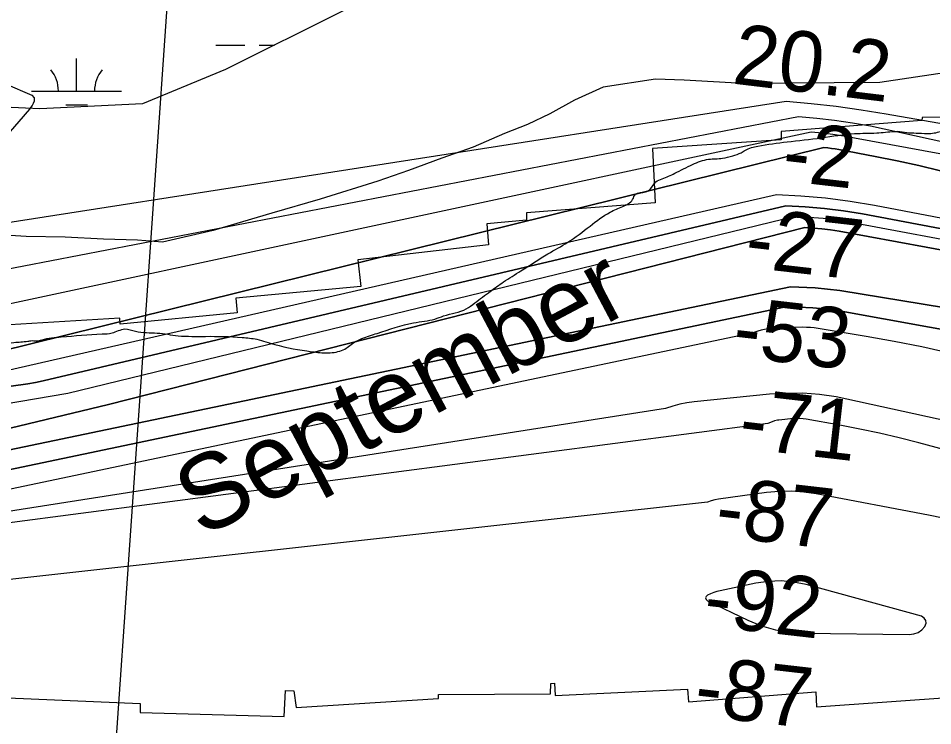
# Model space of a CAD drawing. Extents: x 3445503 to 3483459, y 540493 to 566012.
# Drawn here: x 3466718 to 3467732, y 552212 to 552997 of the extents above; entities that cross this region are included whole.
import ezdxf

# ---------------------------------------------------------------- set-up
doc = ezdxf.new("R2010")
doc.units = 0
for name, color, linetype in [('V-RIVR-EDGE', 7, 'Continuous'), ('V-RIVR-IDEN', 7, 'Continuous'), ('V-RIVR-RANG', 7, 'Continuous'), ('V-RRAP-RVMT', 7, 'Continuous'), ('V-SITE-VEGE', 7, 'Continuous'), ('V-TOPO-DPTH', 7, 'Continuous'), ('V-TOPO-MAJR', 7, 'Continuous'), ('V-TOPO-MINR', 7, 'Continuous'), ('V-TOPO-WATR', 7, 'Continuous'), ('V-WETL-SWMP', 7, 'Continuous')]:
    doc.layers.add(name, color=color, linetype=linetype)

msp = doc.modelspace()

# ---------------------------------------------------------------- linework, layer by layer
at = {"layer": 'V-RIVR-EDGE'}
msp.add_spline([(3466309.4, 552622), (3466349.7, 552619.4), (3466382.7, 552619.3), (3466411.9, 552618.6), (3466431.7, 552619.2), (3466456.4, 552621.2), (3466478.3, 552625.4), (3466500.2, 552626.4), (3466524.2, 552628), (3466536.8, 552627.7), (3466565.6, 552631.8), (3466586.1, 552632.4), (3466600.7, 552633.8), (3466616, 552634.4), (3466639.3, 552633.7), (3466653.6, 552633.6), (3466663.7, 552636.4), (3466671, 552636.7), (3466676.5, 552638.1), (3466689.4, 552636.3), (3466713.4, 552637.3), (3466728.7, 552638.7), (3466733.5, 552639.3), (3466741.2, 552639.3), (3466744.7, 552640.3), (3466765.9, 552643.4), (3466811.1, 552646.8), (3466822.2, 552647.8), (3466836.5, 552652.3), (3466848.3, 552649.8), (3466872.3, 552647.7), (3466895.5, 552644.8), (3466925.8, 552644.1), (3466966.5, 552642.9), (3466982.8, 552640.8), (3467002.6, 552635.2), (3467043.6, 552627.1), (3467061.7, 552625.7), (3467070.7, 552626.7), (3467078.7, 552629.1), (3467090.2, 552637.1), (3467099.3, 552641.6), (3467116.3, 552647.4), (3467156.7, 552659.1), (3467180.3, 552663.3), (3467190, 552666.7), (3467215.1, 552674.6), (3467224.5, 552681.2), (3467241.9, 552694), (3467256.2, 552704.4), (3467275.7, 552716.6), (3467305.6, 552735.6), (3467327.6, 552748.4), (3467352.3, 552766.4), (3467374.6, 552781.7), (3467388.8, 552788.2), (3467399.6, 552795.9), (3467402.8, 552801.8), (3467413.9, 552804.2), (3467419.5, 552807.6), (3467425.4, 552815.3), (3467432.4, 552818.7), (3467446.3, 552824.9), (3467466.1, 552834.6), (3467483.9, 552840.5), (3467499.2, 552841.5), (3467510.7, 552844.3), (3467520, 552847.7), (3467524.6, 552850.5), (3467538.5, 552855), (3467570.8, 552859.7), (3467609.1, 552864.2), (3467645.6, 552868.9), (3467670.3, 552869.6), (3467689.8, 552871.3), (3467696, 552871.3), (3467706.1, 552869.8), (3467716.5, 552869.5), (3467730.4, 552869.1), (3467744.7, 552872.2), (3467757.2, 552874.9), (3467768.3, 552874.9), (3467789.9, 552871.4), (3467862.2, 552872.9), (3467905.6, 552870), (3467943.5, 552856), (3467982, 552836.1), (3468014.6, 552810.7), (3468040.7, 552789.1), (3468070.1, 552766.4), (3468095.1, 552752.4), (3468129.5, 552738.4), (3468159.7, 552729.3), (3468202.1, 552725.4), (3468241.4, 552724.6), (3468263.7, 552723.5), (3468284.5, 552718.6), (3468310.5, 552700.1), (3468339.4, 552679.9), (3468348.4, 552674.3), (3468371.3, 552670), (3468395, 552672.1), (3468423.1, 552672.4), (3468450.6, 552670.5), (3468476.3, 552670.8), (3468493.3, 552672.2), (3468516.3, 552677.3), (3468541.3, 552687.4), (3468560.1, 552697.7), (3468569.5, 552699.5), (3468577.2, 552699.1), (3468586.5, 552693.2), (3468603.2, 552676.1), (3468627.2, 552664.5), (3468668.5, 552659.9), (3468712.7, 552659.1), (3468729.7, 552662.6), (3468746.7, 552667.4), (3468760, 552668.4), (3468773.1, 552661.8), (3468796, 552642.9), (3468815.1, 552632.1), (3468834.6, 552620.2), (3468847.1, 552617.4), (3468885.7, 552611.4), (3468924.9, 552605.1), (3468947.9, 552603.3), (3468956.9, 552605.3), (3468966, 552610.9), (3468970.8, 552616.4), (3468974.7, 552616.4), (3468976.7, 552609.8), (3468983.6, 552592.1), (3468990.6, 552583.7), (3469002.7, 552573.2), (3469014.5, 552565.9), (3469022.2, 552563.1), (3469029.1, 552562.4), (3469038.5, 552560.6), (3469047.9, 552555.4), (3469053.8, 552553.3), (3469073.9, 552550.8), (3469091.3, 552548.3), (3469106.6, 552542), (3469126.7, 552536.4), (3469142.7, 552533.6), (3469153.1, 552532.2), (3469162.5, 552528.3), (3469171.9, 552518.2), (3469185.8, 552509.5), (3469208.7, 552504.6), (3469232.7, 552501.7), (3469258.1, 552503.4), (3469277.2, 552507.5), (3469302.6, 552512.7), (3469341.9, 552520.6), (3469368.3, 552524), (3469396.1, 552521.5), (3469447.9, 552506.1), (3469526, 552476), (3469583.7, 552459.9), (3469651.1, 552445.1), (3469684.8, 552437.7), (3469730.7, 552432.7), (3469767.1, 552428.8), (3469829.7, 552423.4), (3469847.8, 552424.1), (3469856.8, 552424.1), (3469867.6, 552422.3), (3469876.3, 552418.5), (3469887.7, 552412.9), (3469925.6, 552399.2), (3469955.1, 552391.8), (3469977.4, 552385.9), (3470001.3, 552379.6), (3470024.3, 552378.5), (3470048.3, 552381.5), (3470074, 552388.4), (3470084.1, 552390.8), (3470093.8, 552391.5), (3470109.1, 552387.6), (3470138.3, 552373), (3470163.6, 552356.6), (3470192.4, 552345.7), (3470225.5, 552340.4), (3470241.8, 552339.3), (3470271.7, 552339.3), (3470311, 552335.7), (3470330.1, 552335.6), (3470358.6, 552336.3), (3470382.6, 552334.8), (3470398.2, 552331.3), (3470414.5, 552324.7), (3470435, 552316.6), (3470465.6, 552306.1), (3470481.6, 552297), (3470485.4, 552296.3), (3470491.6, 552296), (3470495.8, 552293.5), (3470500, 552290.7), (3470505.9, 552287.9), (3470526.7, 552283), (3470533.3, 552282.7), (3470539.2, 552282.6), (3470542.4, 552281.9), (3470544.1, 552279.5), (3470547.2, 552276.7), (3470551.4, 552273.6), (3470557.6, 552271.8), (3470564.6, 552269.7), (3470576.4, 552270), (3470585.8, 552269.3), (3470591.3, 552266.5), (3470613.6, 552258.5), (3470637.5, 552248), (3470666.7, 552234.4), (3470680.9, 552228.1), (3470696.6, 552223.2), (3470705.2, 552221), (3470710.5, 552221), (3470716.4, 552224.8), (3470726.8, 552226.2), (3470744.9, 552227.9), (3470772, 552229.9), (3470784.2, 552230.6), (3470792.2, 552230.2), (3470802.9, 552227.1), (3470818.6, 552226.7), (3470830.1, 552229.8), (3470836, 552233.6), (3470842.6, 552233.9), (3470861, 552232.8), (3470874.2, 552228.3), (3470890.2, 552221.3), (3470909.3, 552220.5), (3470935.4, 552220.5), (3470949.6, 552223.9), (3470960.8, 552226.3), (3470973.3, 552226.3), (3470997.6, 552221.7), (3471022.3, 552216.4), (3471070.6, 552205.2), (3471089, 552203.4), (3471111.9, 552203), (3471121.7, 552202.6), (3471127.9, 552201.6), (3471132.8, 552198.1), (3471136.6, 552193.2), (3471141.4, 552193.2), (3471145.6, 552196), (3471151.2, 552196.7), (3471156.8, 552196.6), (3471178.3, 552192.1), (3471192.5, 552188.2), (3471223.5, 552180.5), (3471265.8, 552168.6), (3471314.8, 552156.3), (3471351.3, 552145.4), (3471386, 552137), (3471401.3, 552136.6), (3471419.4, 552135.2), (3471433.7, 552132), (3471456.2, 552126.4), (3471476.7, 552123.2), (3471490.6, 552119.3), (3471513.9, 552109.2), (3471547.9, 552099), (3471579.6, 552092), (3471609.4, 552085), (3471637.2, 552078.6), (3471668.5, 552067.4), (3471684.8, 552061.8), (3471699.8, 552059.7), (3471716.4, 552054.5), (3471743.2, 552045.4), (3471759.5, 552035.9), (3471773.4, 552031), (3471788.7, 552023.3), (3471808.5, 552013.9), (3471820.6, 552009), (3471825.8, 552006.2), (3471833.4, 551997.2), (3471837.3, 551992.6), (3471849.4, 551987.4), (3471863.3, 551984.9), (3471900.5, 551985.9), (3471925.9, 551983.7), (3471961.7, 551978.1), (3472004.1, 551970.3), (3472058.3, 551955.6), (3472104.5, 551941.2), (3472151.7, 551925.1), (3472165.6, 551919.9), (3472170.8, 551915.3), (3472181.9, 551909.7), (3472192, 551907.3), (3472200, 551902.4), (3472209, 551898.9), (3472220.1, 551895), (3472235.4, 551890.1), (3472240.6, 551890.1), (3472245.5, 551889.8), (3472259.4, 551886.6), (3472269.4, 551885.2), (3472280.2, 551880.3), (3472294.8, 551878.9), (3472314.3, 551878.1), (3472330.3, 551879.1), (3472344.2, 551880.8), (3472354.3, 551878.7), (3472360.2, 551878.4), (3472367.8, 551879), (3472378.2, 551881.1), (3472386.2, 551881.1), (3472400.5, 551879.3), (3472427.3, 551878.2), (3472454.4, 551882.3), (3472479.8, 551882.9), (3472504.4, 551881.5), (3472524.9, 551881.4), (3472536.4, 551880.7), (3472544.4, 551877.9), (3472549.3, 551875.5), (3472555.2, 551875.4), (3472570.1, 551874.7), (3472580.2, 551875.7), (3472593.4, 551876), (3472610.1, 551875.7), (3472633.7, 551876.3), (3472647.3, 551873.5), (3472654.2, 551870.3), (3472660.1, 551870.3), (3472666.4, 551871.7), (3472682.1, 551871), (3472693.9, 551874.1), (3472707.1, 551879.6), (3472717.9, 551879.9), (3472730.7, 551876.4), (3472741.9, 551876), (3472753.7, 551876.7), (3472772.8, 551883.2), (3472794, 551888.4), (3472814.5, 551891.1), (3472833.3, 551892.8), (3472843.4, 551894.5), (3472860.5, 551899.4), (3472888.3, 551905.6), (3472914, 551910), (3472934.2, 551912.4), (3472958.2, 551913.7), (3472986.3, 551913.7), (3473020.7, 551912.9), (3473048.6, 551912.5), (3473075, 551916.2), (3473094.8, 551921.7), (3473114, 551930.4), (3473134.1, 551940.4), (3473153.3, 551952.2), (3473173.5, 551967.4), (3473183.9, 551974), (3473198.2, 551977.8), (3473219.4, 551975), (3473232.2, 551969), (3473250.3, 551958.5), (3473256.5, 551955.1), (3473269.4, 551952.1)], degree=3, dxfattribs=at)
at = {"layer": 'V-RIVR-RANG'}
msp.add_line((3466910.4, 553408.4), (3466815.3, 552031.7), dxfattribs=at)
at = {"layer": 'V-RRAP-RVMT'}
for points in [[(3468200.7, 552603.7), (3468174.4, 552604.1), (3468177.9, 552877.1), (3468023.7, 552880.9), (3468023.2, 552894.5), (3467863.5, 552892.1), (3467863.5, 552888.5), (3467720.8, 552886.7), (3467720.5, 552883.4), (3467564.5, 552871.2), (3467564.3, 552861.8), (3467421.6, 552852.5)], [(3467421.6, 552852.5), (3467424.7, 552792), (3467281.7, 552780.9), (3467282, 552772.9)], [(3467282, 552772.9), (3467237.8, 552769), (3467239.8, 552745.5), (3467094.7, 552729), (3467098.2, 552699.3), (3466959.6, 552686.5), (3466961, 552670.1), (3466831.2, 552657.6), (3466830.7, 552664.3), (3466696.3, 552656)], [(3467602.6, 552250), (3467603.6, 552233.4), (3467759.6, 552244.3), (3467753.1, 552337.4), (3467871.1, 552339.4), (3467875, 552291.4), (3468016.1, 552292), (3468017, 552266.5), (3468155, 552262.9)], [(3466589, 552268.6), (3466590, 552252.8), (3466706.5, 552261.2), (3466706.6, 552243.3), (3466853.3, 552236.9), (3466853.3, 552227.1), (3467013.2, 552222.5), (3467014.5, 552251.5), (3467024, 552251.2), (3467026.5, 552232.4), (3467184.3, 552242.6), (3467184.1, 552246.9), (3467308.6, 552247.6), (3467308.8, 552259.3)], [(3467308.8, 552259.3), (3467312.8, 552259.6), (3467313.5, 552246), (3467460.6, 552253), (3467461.4, 552239), (3467602.6, 552250)]]:
    msp.add_lwpolyline(points, dxfattribs=at)
at = {"layer": 'V-SITE-VEGE'}
msp.add_lwpolyline([(3467770.2, 552940.1), (3467673.6, 552925.6), (3467521.7, 552924.3), (3467456.8, 552928), (3467425, 552929.1), (3467367, 552920.2), (3467335, 552906), (3467307.7, 552890.9), (3467282.9, 552878.9), (3467257.6, 552869), (3467222.9, 552853.9), (3467188.1, 552841.5), (3467151, 552827.9), (3467117.1, 552816), (3467053.1, 552796), (3466999.4, 552780.5), (3466934.2, 552761.3), (3466878.1, 552748.5), (3466850.5, 552750.8), (3466812.9, 552751.9), (3466770.2, 552754.1), (3466727.1, 552754.8), (3466690.8, 552757)], dxfattribs=at)
at = {"layer": 'V-TOPO-DPTH'}
for points in [[(3468675.4, 552653.6), (3468629.5, 552663.6), (3468583.5, 552674), (3468551.3, 552681.6), (3468521.6, 552688.7), (3467663.3, 552877), (3467643.5, 552880.3), (3467623.6, 552883.3), (3467603.7, 552885.6), (3467583.7, 552887.6), (3466662.5, 552710.1)], [(3468902.4, 552561.7), (3468498.4, 552637.8), (3468490.3, 552639.3), (3468482.1, 552640.9), (3468474, 552642.6), (3468465.9, 552644.3), (3468407.1, 552656.7), (3468018.6, 552753.7), (3467968.3, 552766.8), (3467918, 552780.1), (3467867.8, 552793.5), (3467817.6, 552807.1), (3467765.1, 552821.5), (3467741.1, 552827.7), (3467717.1, 552833.5), (3467692.9, 552838.8), (3467668.7, 552843.6), (3467628.3, 552851.2), (3467624.2, 552851.9), (3467620, 552852.5), (3467615.9, 552853), (3467611.7, 552853.4), (3466656.9, 552617.3)], [(3466656.9, 552617.3), (3467611.7, 552853.4), (3467615.9, 552853), (3467620, 552852.5), (3467624.2, 552851.9), (3467628.3, 552851.2), (3467668.7, 552843.6), (3467692.9, 552838.8), (3467717.1, 552833.5), (3467741.1, 552827.7), (3467765.1, 552821.5), (3467817.6, 552807.1), (3467867.8, 552793.5), (3467918, 552780.1), (3467968.3, 552766.8), (3468018.6, 552753.7), (3468407.1, 552656.7), (3468465.9, 552644.3), (3468474, 552642.6), (3468482.1, 552640.9), (3468490.3, 552639.3), (3468498.4, 552637.8), (3468902.4, 552561.7)], [(3466646.8, 552580.1), (3466728.9, 552591.4), (3466737.4, 552592.9), (3466745.8, 552594.7), (3467569.5, 552788.9), (3467590.9, 552787.8), (3467612.3, 552786), (3467633.5, 552783.2), (3467654.7, 552779.8), (3467909, 552731.7), (3468004, 552713.4), (3468098.9, 552694.7), (3468193.6, 552675.2), (3468288.3, 552655.4), (3468435.6, 552623.9), (3468456.5, 552619.4), (3468477.5, 552615), (3468498.5, 552610.6), (3468519.5, 552606.3), (3468633.1, 552582.9), (3468710.9, 552566.8)], [(3466646.8, 552580.1), (3466728.9, 552591.4), (3466737.4, 552592.9), (3466745.8, 552594.7), (3467569.5, 552788.9), (3467590.9, 552787.8), (3467612.3, 552786), (3467633.5, 552783.2), (3467654.7, 552779.8), (3467909, 552731.7), (3468004, 552713.4), (3468098.9, 552694.7), (3468193.6, 552675.2), (3468288.3, 552655.4), (3468435.6, 552623.9), (3468456.5, 552619.4), (3468477.5, 552615), (3468498.5, 552610.6), (3468519.5, 552606.3), (3468633.1, 552582.9), (3468710.9, 552566.8)], [(3469058.5, 552438.2), (3468619.7, 552554.3), (3468583, 552562.7), (3468546.2, 552570.9), (3468500.4, 552580.8), (3468486.5, 552583.8), (3468472.5, 552586.8), (3468458.5, 552589.8), (3468444.5, 552592.8), (3467955.6, 552697.2), (3467898.1, 552709.2), (3467840.6, 552720.9), (3467782.9, 552732.1), (3467725.2, 552742.9), (3467628.6, 552760.7), (3467619.1, 552762.2), (3467609.6, 552763.4), (3467600.1, 552764.2), (3467590.5, 552764.7), (3466818.1, 552568.6), (3466610.5, 552518.6)], [(3466610.5, 552518.6), (3466818.1, 552568.6), (3467590.5, 552764.7), (3467600.1, 552764.2), (3467609.6, 552763.4), (3467619.1, 552762.2), (3467628.6, 552760.7), (3467725.2, 552742.9), (3467782.9, 552732.1), (3467840.6, 552720.9), (3467898.1, 552709.2), (3467955.6, 552697.2), (3468444.5, 552592.8), (3468458.5, 552589.8), (3468472.5, 552586.8), (3468486.5, 552583.8), (3468500.4, 552580.8), (3468546.2, 552570.9), (3468583, 552562.7), (3468619.7, 552554.3), (3469058.5, 552438.2)], [(3469105.8, 552361.2), (3468472, 552554.4), (3468467, 552555.8), (3468461.9, 552557.1), (3468456.9, 552558.4), (3468451.8, 552559.5), (3468446.7, 552560.6), (3468441.6, 552561.6), (3468436.5, 552562.5), (3467629.3, 552695), (3467602, 552697.7), (3467574.7, 552698.9), (3466614.6, 552498.8)], [(3466614.6, 552498.8), (3467574.7, 552698.9), (3467602, 552697.7), (3467629.3, 552695), (3468436.5, 552562.5), (3468441.6, 552561.6), (3468446.7, 552560.6), (3468451.8, 552559.5), (3468456.9, 552558.4), (3468461.9, 552557.1), (3468467, 552555.8), (3468472, 552554.4), (3469105.8, 552361.2)], [(3469044.2, 552331), (3468606.4, 552466.6), (3468564.4, 552478.7), (3468505.5, 552495.2), (3468482, 552501.6), (3468458.4, 552507.8), (3468434.7, 552513.7), (3468410.9, 552519.4), (3468264.8, 552553.3), (3468167.8, 552574.9), (3467630.8, 552672), (3467615.2, 552674.2), (3467599.4, 552675.8), (3467583.6, 552676.5), (3467567.8, 552676.6), (3466631.4, 552480.1)], [(3466631.4, 552480.1), (3467567.8, 552676.6), (3467583.6, 552676.5), (3467599.4, 552675.8), (3467615.2, 552674.2), (3467630.8, 552672), (3468167.8, 552574.9), (3468264.8, 552553.3), (3468410.9, 552519.4), (3468434.7, 552513.7), (3468458.4, 552507.8), (3468482, 552501.6), (3468505.5, 552495.2), (3468564.4, 552478.7), (3468606.4, 552466.6), (3469044.2, 552331)]]:
    msp.add_lwpolyline(points, dxfattribs=at)
at = {"layer": 'V-TOPO-MAJR'}
msp.add_lwpolyline([(3468445.6, 552466.8), (3467720.3, 552632.4), (3467689.5, 552638.3), (3467658.6, 552643.8), (3467605.3, 552652.8), (3467601.1, 552653.4), (3467596.8, 552653.9), (3467592.5, 552654), (3467588.2, 552654.1), (3467560.2, 552653.5), (3467556.5, 552653.3), (3467552.9, 552653), (3467549.3, 552652.4), (3467545.7, 552651.6), (3467542.1, 552650.8), (3467538.6, 552649.8), (3467535, 552648.8), (3467531.5, 552647.7), (3466648, 552461.6)], dxfattribs=at)
at = {"layer": 'V-TOPO-MINR'}
for points in [[(3466674.4, 552936.7), (3466733.1, 552911.4), (3466735.8, 552908.6), (3466735.9, 552904.7), (3466734.8, 552902.4), (3466733.6, 552900.2), (3466732.2, 552898.1), (3466730.7, 552896.1), (3466661.5, 552816.5)], [(3468865.4, 552666.8), (3468512.1, 552741.5), (3468506.3, 552742.7), (3468500.5, 552743.9), (3468494.7, 552745.2), (3468488.9, 552746.4), (3468448.8, 552755.1), (3468422.9, 552760.5), (3468397, 552765.7), (3467680.8, 552890.4), (3467653.2, 552894.9), (3467625.5, 552898.8), (3467597.6, 552902), (3467569.8, 552904.6), (3466621, 552756.7)], [(3468675.4, 552653.6), (3468629.5, 552663.6), (3468583.5, 552674), (3468551.3, 552681.6), (3468521.6, 552688.7), (3467663.3, 552877), (3467643.5, 552880.3), (3467623.6, 552883.3), (3467603.7, 552885.6), (3467583.7, 552887.6), (3466662.5, 552710.1)], [(3469069.5, 552548.3), (3468488.6, 552652), (3468484.3, 552652.8), (3468482.1, 552653.2), (3468479.9, 552653.7), (3468463.4, 552657.1), (3467762.3, 552842.2), (3467645.8, 552864), (3467633.8, 552866.1), (3467621.8, 552867.9), (3467609.8, 552869.3), (3467597.7, 552870.5), (3466638.4, 552665.1)], [(3468749.7, 552574.9), (3468508.7, 552622.5), (3468494.3, 552625.4), (3468479.9, 552628.3), (3468465.5, 552631.3), (3468451.1, 552634.3), (3468349.4, 552656), (3468284.1, 552669.7), (3468153.3, 552696.1), (3468087.8, 552708.9), (3467667.7, 552789.2), (3467640.7, 552793.7), (3467613.6, 552797.3), (3467586.3, 552799.6), (3467559, 552801), (3466700.3, 552604.9)], [(3468710.9, 552566.8), (3468633.1, 552582.9), (3468519.5, 552606.3), (3468498.5, 552610.6), (3468477.5, 552615), (3468456.5, 552619.4), (3468435.6, 552623.9), (3468288.3, 552655.4), (3468193.6, 552675.2), (3468098.9, 552694.7), (3468004, 552713.4), (3467909, 552731.7), (3467654.7, 552779.8), (3467633.5, 552783.2), (3467612.3, 552786), (3467590.9, 552787.8), (3467569.5, 552788.9), (3466745.8, 552594.7), (3466737.4, 552592.9), (3466728.9, 552591.4), (3466646.8, 552580.1)], [(3468700, 552551.9), (3468643.9, 552564.7), (3468587.7, 552577.1), (3468517.2, 552592.1), (3468496.1, 552596.6), (3468475, 552601.1), (3468454, 552605.6), (3468432.9, 552610.2), (3468153.6, 552669.9), (3468063.4, 552688.8), (3467973.2, 552707.2), (3467882.7, 552724.9), (3467792.2, 552742.2), (3467641.7, 552770.2), (3467626.3, 552772.7), (3467611, 552774.7), (3467595.5, 552776), (3467580, 552776.8), (3466773.3, 552580.8), (3466666.4, 552562.7)], [(3469058.5, 552438.2), (3468619.7, 552554.3), (3468583, 552562.7), (3468546.2, 552570.9), (3468500.4, 552580.8), (3468486.5, 552583.8), (3468472.5, 552586.8), (3468458.5, 552589.8), (3468444.5, 552592.8), (3467955.6, 552697.2), (3467898.1, 552709.2), (3467840.6, 552720.9), (3467782.9, 552732.1), (3467725.2, 552742.9), (3467628.6, 552760.7), (3467619.1, 552762.2), (3467609.6, 552763.4), (3467600.1, 552764.2), (3467590.5, 552764.7), (3466818.1, 552568.6), (3466610.5, 552518.6)], [(3469105.8, 552361.2), (3468472, 552554.4), (3468467, 552555.8), (3468461.9, 552557.1), (3468456.9, 552558.4), (3468451.8, 552559.5), (3468446.7, 552560.6), (3468441.6, 552561.6), (3468436.5, 552562.5), (3467629.3, 552695), (3467602, 552697.7), (3467574.7, 552698.9), (3466614.6, 552498.8)], [(3469044.2, 552331), (3468606.4, 552466.6), (3468564.4, 552478.7), (3468505.5, 552495.2), (3468482, 552501.6), (3468458.4, 552507.8), (3468434.7, 552513.7), (3468410.9, 552519.4), (3468264.8, 552553.3), (3468167.8, 552574.9), (3467630.8, 552672), (3467615.2, 552674.2), (3467599.4, 552675.8), (3467583.6, 552676.5), (3467567.8, 552676.6), (3466631.4, 552480.1)], [(3468785.6, 552307.5), (3468643.5, 552341.6), (3468609.2, 552350), (3468574.9, 552358.6), (3468540.7, 552367.6), (3468506.6, 552376.8), (3468501.8, 552378.1), (3468470.1, 552386.8), (3468438.4, 552395.6), (3468406.7, 552404.3), (3468375, 552413), (3467625.3, 552577), (3467606.9, 552579.5), (3467588.4, 552581), (3467569.9, 552580.9), (3467551.3, 552579.8), (3467467.9, 552571.5), (3467459.8, 552570.4), (3467451.8, 552568.9), (3467444, 552566.7), (3467436.2, 552564.2), (3466664.3, 552443.3)], [(3467780.1, 552509), (3467717.1, 552525.9), (3467695.3, 552531.4), (3467673.4, 552536.6), (3467651.4, 552541.3), (3467629.3, 552545.5), (3467592.1, 552552.3), (3467588.6, 552552.8), (3467585, 552553.1), (3467581.4, 552553.1), (3467577.9, 552552.9), (3467561.8, 552551.3), (3467560.2, 552551), (3467557.1, 552550.3), (3467552.6, 552548.7), (3467549.5, 552547.6), (3466617.9, 552425.5)], [(3467803.4, 552430.4), (3467727.6, 552445.7), (3467603.1, 552469.5), (3467589.5, 552471.4), (3467575.7, 552472.5), (3467562, 552472.1), (3467548.2, 552470.9), (3467495, 552463.5), (3467490.8, 552462.7), (3467486.7, 552461.7), (3467482.8, 552460.2), (3466625, 552365.1)], [(3467480.5, 552354), (3467481.1, 552352.4), (3467482.6, 552350.8), (3467527.5, 552329.3), (3467542.6, 552323.3), (3467557.9, 552318.7), (3467573.8, 552316.1), (3467589.9, 552314.9), (3467706.4, 552313.7), (3467711.5, 552314.4), (3467716.1, 552315.9), (3467720.2, 552318.7), (3467723.8, 552322.3), (3467725, 552325.9), (3467724.9, 552329.1), (3467723, 552331.7), (3467719.8, 552333.9), (3467592.1, 552368.8), (3467578.1, 552371.5), (3467564.2, 552372.9), (3467550.2, 552372.3), (3467536.1, 552370.4), (3467496.7, 552362), (3467493.1, 552361.1), (3467489.5, 552360.1), (3467486, 552358.7), (3467482.6, 552357.2), (3467481.1, 552355.6), (3467480.5, 552354)]]:
    msp.add_lwpolyline(points, dxfattribs=at)
at = {"layer": 'V-TOPO-WATR'}
msp.add_lwpolyline([(3468902.4, 552561.7), (3468498.4, 552637.8), (3468490.3, 552639.3), (3468482.1, 552640.9), (3468474, 552642.6), (3468465.9, 552644.3), (3468407.1, 552656.7), (3468018.6, 552753.7), (3467968.3, 552766.8), (3467918, 552780.1), (3467867.8, 552793.5), (3467817.6, 552807.1), (3467765.1, 552821.5), (3467741.1, 552827.7), (3467717.1, 552833.5), (3467692.9, 552838.8), (3467668.7, 552843.6), (3467628.3, 552851.2), (3467624.2, 552851.9), (3467620, 552852.5), (3467615.9, 552853), (3467611.7, 552853.4), (3466656.9, 552617.3)], dxfattribs=at)
at = {"layer": 'V-WETL-SWMP'}
for p, q in [((3466937.4, 552966.9), (3466969.4, 552966.9)), ((3466985.4, 552966.9), (3467002.3, 552966.9)), ((3466782.8, 552916.1), (3466782.8, 552952.1)), ((3466732.8, 552916.1), (3466832.8, 552916.1)), ((3466770.8, 552900.7), (3466794.8, 552900.7))]:
    msp.add_line(p, q, dxfattribs=at)
msp.add_lwpolyline([(3467744.4, 553070.9), (3467691.9, 553078.8), (3467643.5, 553082.5), (3467615.4, 553070.1), (3467555.8, 553042.9), (3467452.7, 553021.2), (3467360.5, 553015.8), (3467295.4, 553026.7), (3467224.8, 553042.9), (3467078.4, 553005), (3466948.2, 552939.9), (3466855.9, 552901.9), (3466742, 552896.5), (3466622.7, 552901.9)], dxfattribs=at)
for centre, start, end in [((3466727.5, 552916.6), 359.2282, 40.7719), ((3466838, 552916.6), 139.2282, 180.7718)]:
    msp.add_arc(centre, 35.2, start, end, dxfattribs=at)

# ---------------------------------------------------------------- texts
at = {"layer": 'V-RIVR-IDEN'}
msp.add_text('September', height=83, rotation=27.8905, dxfattribs=at).set_placement((3466921.6, 552419.9))
at = {"layer": 'V-RIVR-RANG'}
for s, rotation, p in [('20.2', 353.1783, (3467508.9, 552924.5)), ('-2', 353.4611, (3467563.7, 552817)), ('-27', 353.4611, (3467522.4, 552721.1)), ('-53', 353.4611, (3467508.9, 552622)), ('-71', 353.4611, (3467515.9, 552520.5)), ('-87', 353.4611, (3467489.6, 552422.9)), ('-92', 353.4611, (3467476.7, 552323.7)), ('-87', 353.4611, (3467466.3, 552224.2))]:
    msp.add_text(s, height=67, rotation=rotation, dxfattribs=at).set_placement(p)

doc.saveas('drawing.dxf')
